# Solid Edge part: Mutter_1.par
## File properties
Sűrűség: 0,000 kg/m^3
Pontosság: 0,990
Author: ahadarics
Last saved by: ahadarics
Revision: 76
Username: ahadarics
Dokumentum tartalom típus: 0
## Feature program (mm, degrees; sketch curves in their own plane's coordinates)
base feature "unnamed BaseFeature 1"
thread "unnamed Thread 1"
chamfer "unnamed Chamfer 1"
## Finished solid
Body 1: solid body, 13 faces, 24 edges, 12 vertices.
  Faces by surface: plane 8, cone 4, cylinder 1
  Edges by curve: spline 12, circle 6, line 6
Bounding box of the edges (mm): 31.177 x 27.000 x 8.000, from (-15.5885, -13.5, -4) to (15.5885, 13.5, 4).
Cylindrical faces by radius (mm): R10.188 x1
Conical faces (half-angle, radius in mm at the cone's reference point): 45 deg R10.188 x1, 45 deg R11.188 x1, 75 deg R14.5 x2
Planar faces by outward normal: +y 1, +z 1, -y 1, -z 1, oblique 4
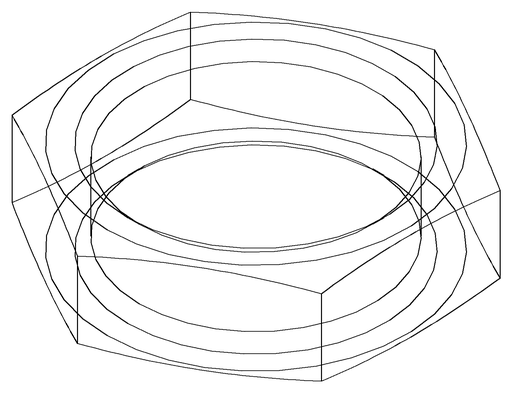
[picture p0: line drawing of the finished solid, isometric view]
